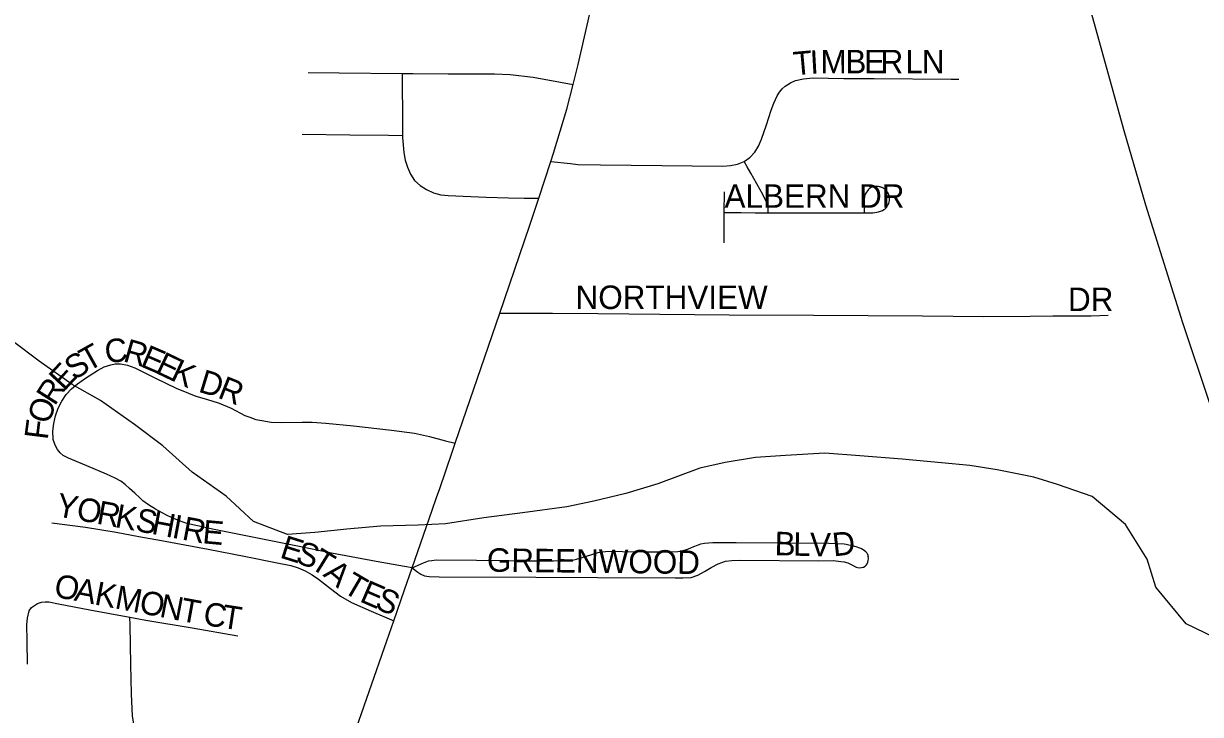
# Model space of a CAD drawing. Extents: x 1985906 to 2360102, y 891258 to 1222054.
# Drawn here: x 2125135 to 2127638, y 1031020 to 1032490 of the extents above; entities that cross this region are included whole.
import ezdxf

# ---------------------------------------------------------------- set-up
doc = ezdxf.new("R2010")
doc.units = 0
for name, color, linetype in [('GM_X_City_Street', 7, 'Continuous'), ('GM_X_City_Street_Text', 7, 'Continuous'), ('GM_X_Minor_River', 7, 'Continuous'), ('GM_X_State_Route', 7, 'Continuous')]:
    doc.layers.add(name, color=color, linetype=linetype)

msp = doc.modelspace()

# ---------------------------------------------------------------- linework, layer by layer
at = {"layer": 'GM_X_City_Street'}
for points in [[(2126304.1, 1032360), (2126315.1, 1032402.4), (2126347.3, 1032546), (2126373.3, 1032674.3), (2126396.4, 1032803.1), (2126414.3, 1032916.1), (2126433.4, 1033062), (2126441.7, 1033148.8)], [(2125740.4, 1032385.4), (2125806.6, 1032385), (2125940.4, 1032383.6)], [(2125940.4, 1032383.6), (2125963.2, 1032383.4), (2126038.4, 1032383), (2126087.8, 1032382.9), (2126137.2, 1032382.7), (2126170.1, 1032381), (2126219.4, 1032375.6), (2126277.5, 1032364.9), (2126304.1, 1032360)], [(2125940.4, 1032383.6), (2125940.6, 1032344), (2125940.9, 1032311.7), (2125941.4, 1032251.6)], [(2126256.8, 1032196.3), (2126262.6, 1032213.8), (2126290.5, 1032307.7), (2126304.1, 1032360)], [(2126668, 1032195.9), (2126680.2, 1032204.6), (2126690.5, 1032215.8), (2126698.4, 1032229.1), (2126705, 1032243.5), (2126715.4, 1032273.8), (2126725, 1032305.1), (2126730.8, 1032320.3), (2126737.8, 1032335.5), (2126743.3, 1032344), (2126749, 1032350.7), (2126754.7, 1032356.1), (2126766.3, 1032363.6), (2126777, 1032368.3), (2126793.9, 1032372), (2126814.6, 1032374), (2126880.1, 1032372.9), (2126944.3, 1032372.5), (2127107.9, 1032371.6), (2127124.5, 1032371.6)], [(2125727.7, 1032254.1), (2125829.2, 1032253.1), (2125911.7, 1032252), (2125941.4, 1032251.6)], [(2125941.4, 1032251.6), (2125941.4, 1032247.3), (2125944.1, 1032215.2), (2125947.2, 1032199.3), (2125951.7, 1032183.9), (2125958, 1032169.1), (2125967.1, 1032155.8), (2125979, 1032145), (2125992.6, 1032136.4), (2126007.2, 1032129.6), (2126022.7, 1032125.2), (2126038.7, 1032123.5), (2126086.7, 1032121.6), (2126118.9, 1032120.4), (2126166.9, 1032119), (2126200.2, 1032118.4), (2126231, 1032117.9)], [(2126231, 1032117.9), (2126256.8, 1032196.3)], [(2126256.8, 1032196.3), (2126298.2, 1032191.8), (2126313.8, 1032190.1), (2126362.5, 1032189), (2126427.7, 1032188.2), (2126622.8, 1032186.3), (2126638.7, 1032187.3), (2126653.9, 1032190.3), (2126668, 1032195.9)], [(2126719, 1032087.2), (2126719, 1032094.1), (2126718.8, 1032097.1), (2126718.8, 1032099.5), (2126718.6, 1032102.2), (2126718.2, 1032103.6), (2126717.7, 1032105), (2126716.3, 1032108.1), (2126707.3, 1032125.7), (2126682.1, 1032171), (2126674.3, 1032184.8), (2126668, 1032195.9)], [(2126625.6, 1032087.7), (2126625.8, 1032131.9)], [(2126719, 1032087.2), (2126841.3, 1032087), (2126896.4, 1032086.6), (2126941.3, 1032087.2), (2126949.9, 1032088.1), (2126953.8, 1032089), (2126957.7, 1032090.3), (2126961.9, 1032091.9), (2126965.1, 1032093.7), (2126966.7, 1032094.9), (2126968.4, 1032096.4), (2126969.9, 1032097.9), (2126971, 1032099.5), (2126972.3, 1032101.3), (2126973.4, 1032103), (2126974.3, 1032104.6), (2126975.2, 1032106.8), (2126976.5, 1032110.6), (2126976.9, 1032113.4), (2126977.1, 1032115.2), (2126977, 1032117.1), (2126976.7, 1032119.4), (2126975.9, 1032123.4), (2126974.5, 1032127), (2126972.7, 1032130.6), (2126971.6, 1032132.3), (2126970.1, 1032134.1), (2126968.7, 1032135.4), (2126967.4, 1032136.6), (2126965.5, 1032138.1), (2126963.9, 1032139.1), (2126961.5, 1032140.5), (2126959.6, 1032141.1), (2126957.4, 1032142), (2126955.5, 1032142.5), (2126953.7, 1032142.9), (2126951.6, 1032143.2), (2126949.4, 1032143.3), (2126947.1, 1032143.2), (2126944.5, 1032142.9), (2126942.5, 1032142.5), (2126939.5, 1032141.4), (2126936.5, 1032139.8), (2126934, 1032137.9), (2126931.8, 1032135.8), (2126930, 1032133.8), (2126928, 1032131.2), (2126926.4, 1032128.8), (2126925.5, 1032126.9), (2126924.5, 1032124.6), (2126923.8, 1032122.1), (2126923.4, 1032119.6), (2126923.1, 1032117.1), (2126923, 1032113.4), (2126922.9, 1032088.7)], [(2126148, 1031873.7), (2126211.5, 1032058.4), (2126231, 1032117.9)], [(2126625.3, 1032023.2), (2126625.6, 1032087.7)], [(2126625.6, 1032087.7), (2126635.6, 1032087.6), (2126661.5, 1032087.6), (2126691.4, 1032087.2), (2126719, 1032087.2)], [(2126053.2, 1031596.7), (2126131.6, 1031826), (2126148, 1031873.7)], [(2126148, 1031873.7), (2126188.2, 1031873.6), (2126260.4, 1031873.3), (2126356.8, 1031873), (2126488.3, 1031871.5), (2126635.6, 1031870), (2126815.5, 1031869.3), (2127046.8, 1031867.6), (2127177.7, 1031866.1), (2127275.8, 1031867.4), (2127324.6, 1031867.6), (2127405.8, 1031867.5), (2127442.1, 1031869.2)], [(2125961.7, 1031331.5), (2125945.7, 1031334.3), (2125885.4, 1031345), (2125790.1, 1031363.2), (2125714.2, 1031378.3), (2125633.2, 1031394.5), (2125541, 1031413.5), (2125505.2, 1031420.7), (2125482.9, 1031426.3), (2125467.3, 1031431.4), (2125451.1, 1031438.1), (2125439.5, 1031443.4), (2125415.9, 1031456.5), (2125400.8, 1031466), (2125389.1, 1031474.4), (2125382.9, 1031480.5), (2125371.8, 1031490.6), (2125360.6, 1031500.7), (2125351.1, 1031509), (2125342.2, 1031515.8), (2125329.9, 1031522.4), (2125312, 1031530.8), (2125269.6, 1031548.7), (2125230.7, 1031565.3), (2125219.9, 1031570.5), (2125213.1, 1031576.1), (2125207.6, 1031583.3), (2125202.5, 1031592.9), (2125198.2, 1031604.9), (2125197.4, 1031622.3), (2125199.7, 1031638.8), (2125203.6, 1031655.1), (2125209.1, 1031671), (2125216.4, 1031686.2), (2125225.7, 1031700.3), (2125237.1, 1031712.7), (2125249.8, 1031723), (2125266.8, 1031735.3), (2125292.5, 1031751.5), (2125307, 1031759.3), (2125321.2, 1031763.7), (2125330.5, 1031765.4), (2125341.6, 1031766), (2125356.1, 1031763.1), (2125372, 1031757.1), (2125416.1, 1031735), (2125460.2, 1031714), (2125485.8, 1031703.4), (2125501.4, 1031697.2), (2125519.8, 1031692.2), (2125535.4, 1031687.2), (2125551.1, 1031682.2), (2125576.8, 1031671), (2125605.9, 1031655.9), (2125616.5, 1031652.1), (2125629.3, 1031647.5), (2125641.9, 1031644.8), (2125661.7, 1031641.3), (2125683.5, 1031640.8), (2125728.2, 1031641.3), (2125748.8, 1031641.3), (2125778.4, 1031639.6), (2125836.7, 1031634), (2125917.9, 1031624.9), (2125966.5, 1031617.9), (2125998.8, 1031611.1), (2126032.6, 1031602.2), (2126053.2, 1031596.7)], [(2126013.7, 1031481.5), (2126020.3, 1031500.4), (2126046.7, 1031577.7), (2126053.2, 1031596.7)], [(2125961.7, 1031331.5), (2126004.1, 1031454.2), (2126013.7, 1031481.5)], [(2125195.7, 1031427.6), (2125267, 1031418), (2125332.1, 1031407.3), (2125380.4, 1031398.3), (2125428.8, 1031390.1), (2125527.7, 1031371.5), (2125607.8, 1031355.5), (2125671.2, 1031343), (2125703.6, 1031336.4), (2125719.4, 1031331.6), (2125734.5, 1031325.1), (2125749, 1031317.1), (2125762.4, 1031307.7), (2125788.2, 1031287.9), (2125809.5, 1031271.7), (2125832.8, 1031257.8), (2125874.4, 1031239.2), (2125902.7, 1031227.2), (2125922.5, 1031218.8)], [(2125961.7, 1031331.5), (2125985.7, 1031342.6), (2125996.2, 1031346.2), (2126003.8, 1031347.6), (2126012.9, 1031348.4), (2126098.9, 1031347.9), (2126196.9, 1031346.7), (2126262.3, 1031346.3), (2126293, 1031347.3), (2126302.5, 1031348.3), (2126311, 1031350.1), (2126342, 1031359.1), (2126357.7, 1031364), (2126365.5, 1031365.7), (2126373.2, 1031366.5), (2126388.9, 1031366.8), (2126409.4, 1031366.5), (2126456.6, 1031365.8), (2126505.9, 1031365.5), (2126526.9, 1031366.7), (2126535.4, 1031368), (2126542.8, 1031369.7), (2126549.4, 1031371.8), (2126554.7, 1031374.2), (2126560.7, 1031376.7), (2126568.7, 1031380.1), (2126575.9, 1031382.4), (2126583.8, 1031384.1), (2126592.3, 1031385), (2126601, 1031385.6), (2126622.8, 1031385.5), (2126650.9, 1031385.4), (2126848.2, 1031383.8), (2126880.8, 1031382.6), (2126885, 1031381.9), (2126890.5, 1031380.9), (2126897.3, 1031379.3), (2126905.2, 1031377), (2126913.1, 1031374.4), (2126917.3, 1031372.8), (2126920.9, 1031371), (2126924.1, 1031368.8), (2126926.4, 1031366.6), (2126927.6, 1031365.3), (2126928.9, 1031363.4), (2126930.1, 1031361), (2126931.8, 1031355.8)], [(2125961.7, 1031331.5), (2125973.8, 1031322.1), (2125980.3, 1031318.2), (2125988.1, 1031314.8), (2125998.1, 1031312.9), (2126019.2, 1031312.7), (2126224.6, 1031311.9), (2126356.2, 1031311.1), (2126520.8, 1031310.2), (2126537.2, 1031310.6), (2126554.8, 1031311.1), (2126569.4, 1031315.8), (2126583.7, 1031324), (2126597.8, 1031332.6), (2126612.4, 1031340.1), (2126627.8, 1031346), (2126641.8, 1031347.5), (2126660.4, 1031348.3), (2126825.1, 1031346.9), (2126858, 1031347), (2126873.7, 1031345.4), (2126880.5, 1031344.4), (2126888.3, 1031342.3), (2126897.1, 1031338.1), (2126906, 1031333.3), (2126909.2, 1031332.1), (2126913, 1031331.7), (2126917.5, 1031332.4), (2126921.6, 1031333.4), (2126924.9, 1031335.3), (2126927.4, 1031337.5), (2126929.5, 1031340.4), (2126930.8, 1031343.5), (2126931.8, 1031347.4), (2126932.1, 1031351.3), (2126931.8, 1031355.8)], [(2125922.5, 1031218.8), (2125945.4, 1031284.5), (2125961.7, 1031331.5)], [(2125144, 1031127), (2125142.9, 1031175.6), (2125142.4, 1031211.3), (2125143.7, 1031224.5), (2125147.6, 1031239.9), (2125152.5, 1031247.1), (2125158.3, 1031251.7), (2125165.3, 1031255.6), (2125173.3, 1031258.8), (2125181.3, 1031259.3), (2125189, 1031259), (2125209.6, 1031255.1), (2125276.3, 1031242.2), (2125361.4, 1031226.5)], [(2125361.4, 1031226.5), (2125395.2, 1031220.3), (2125493.9, 1031203.8), (2125590.8, 1031187.1)], [(2125376.6, 1030838.3), (2125376.5, 1030853.9), (2125376.5, 1030884.3), (2125376, 1030904), (2125374.9, 1030920.1), (2125372.3, 1030966.5), (2125370.7, 1030984.1), (2125369, 1031003.3), (2125367.3, 1031016.5), (2125365.5, 1031047.4), (2125364.7, 1031063.9), (2125363.7, 1031125.9), (2125361.8, 1031209.8), (2125361.4, 1031226.5)], [(2125791.8, 1030836.5), (2125803.3, 1030870.7), (2125833.1, 1030960.5), (2125907.8, 1031176.7), (2125922.5, 1031218.8)]]:
    msp.add_lwpolyline(points, dxfattribs=at)
at = {"layer": 'GM_X_Minor_River'}
msp.add_lwpolyline([(2127668.1, 1031183.1), (2127607.9, 1031212.7), (2127543.4, 1031290.3), (2127525, 1031350.3), (2127478.5, 1031424), (2127408.1, 1031483.6), (2127333.9, 1031509), (2127283.8, 1031524.7), (2127205.7, 1031540.1), (2127147.6, 1031549.7), (2127087.6, 1031555.2), (2127003.6, 1031562.6), (2126913.5, 1031570), (2126839.5, 1031575.4), (2126755.5, 1031570.8), (2126691.6, 1031566.3), (2126627.7, 1031555.8), (2126573.8, 1031543.4), (2126484, 1031510.7), (2126416.1, 1031490.1), (2126348.3, 1031473.6), (2126290.4, 1031461.2), (2126196.5, 1031448.4), (2126114.5, 1031437.8), (2126032.6, 1031425.2), (2125974.7, 1031422.7), (2125894.7, 1031420.1), (2125822.7, 1031413.6), (2125754.8, 1031407.1), (2125696.8, 1031402.6), (2125624.6, 1031430.1), (2125566.3, 1031483.8), (2125493.9, 1031535.3), (2125431.6, 1031590.9), (2125371.3, 1031636.5), (2125298.9, 1031688), (2125238.7, 1031721.6), (2125168.4, 1031771.1), (2125114.1, 1031812.8)], dxfattribs=at)
at = {"layer": 'GM_X_State_Route'}
msp.add_lwpolyline([(2127658, 1031681.3), (2127601, 1031852.8), (2127521.7, 1032103.3), (2127475.7, 1032261.1), (2127405.9, 1032514.4), (2127344.9, 1032752.8), (2127279.2, 1033007.3), (2127209.2, 1033276.4), (2127162.6, 1033451.6), (2127127, 1033559)], dxfattribs=at)

# ---------------------------------------------------------------- texts
at = {"layer": 'GM_X_City_Street_Text'}
for s, rotation, p in [('T', 5.1994, (2126774.4, 1032379.2)), ('I', 3.1047, (2126809, 1032382.4)), ('M', 0.1821, (2126830.3, 1032383.5)), ('B', 0, (2126883.1, 1032383.7)), ('E', 0, (2126922.7, 1032383.7)), ('R', 0, (2126957.9, 1032383.7)), ('L', 0, (2127010.6, 1032383.7)), ('N', 0, (2127045.8, 1032383.7)), ('ALBERN DR', 0, (2126626.1, 1032097.7)), ('NORTHVIEW', 0, (2126309.3, 1031882.3)), ('DR', 0, (2127356.5, 1031877.9)), ('T', 29.0095, (2125272, 1031748)), ('C', 6.4984, (2125310.7, 1031766.7)), ('R', 344.0613, (2125344.9, 1031771.6)), ('E', 336.7476, (2125381.4, 1031761.3)), ('S', 32.379, (2125242.9, 1031729.6)), ('E', 334.4615, (2125413.2, 1031747.6)), ('E', 47.0482, (2125221.5, 1031706)), ('K', 334.8864, (2125445.4, 1031732.3)), ('R', 57.6368, (2125201.8, 1031674.5)), ('D', 343.0892, (2125505.1, 1031706.8)), ('R', 338.2302, (2125546.1, 1031694.4)), ('O', 73.127, (2125190.5, 1031635.6)), ('F', 82.8242, (2125186.6, 1031602.8)), ('Y', 349.4273, (2125202.3, 1031442.1)), ('O', 349.4059, (2125245.6, 1031434.1)), ('R', 349.4284, (2125288.8, 1031426)), ('K', 349.4273, (2125327.8, 1031418.7)), ('S', 349.419, (2125371, 1031410.6)), ('H', 349.4059, (2125405.6, 1031404.2)), ('I', 349.4292, (2125448.9, 1031396.1)), ('R', 349.3997, (2125470.5, 1031392.1)), ('E', 354.7328, (2125514.5, 1031384.1)), ('B', 358.4696, (2126732, 1031358.7)), ('L', 358.4674, (2126771.6, 1031357.6)), ('V', 358.4891, (2126806.8, 1031356.7)), ('D', 6.3721, (2126858.2, 1031355.8)), ('E', 342.5498, (2125678.3, 1031354)), ('S', 340.5888, (2125711.4, 1031343.5)), ('T', 328.1742, (2125742, 1031333.1)), ('GREENWOOD', 359.3631, (2126120.4, 1031323.5)), ('A', 319.6879, (2125770.4, 1031315.7)), ('O', 349.183, (2125197.9, 1031270.5)), ('A', 349.183, (2125241.1, 1031262.3)), ('T', 329.6341, (2125811.6, 1031281.7)), ('E', 336.5928, (2125847.9, 1031260.9)), ('K', 349.183, (2125284.3, 1031254)), ('M', 349.1856, (2125327.5, 1031245.8)), ('O', 349.183, (2125379.4, 1031235.9)), ('S', 335.7324, (2125880, 1031247)), ('N', 349.183, (2125422.6, 1031227.6)), ('T', 349.7085, (2125466.3, 1031219.2)), ('C', 351.2166, (2125515.4, 1031210.5)), ('T', 351.2323, (2125554.6, 1031204.5))]:
    msp.add_text(s, height=50, rotation=rotation, dxfattribs=at).set_placement(p)

doc.saveas('drawing.dxf')
